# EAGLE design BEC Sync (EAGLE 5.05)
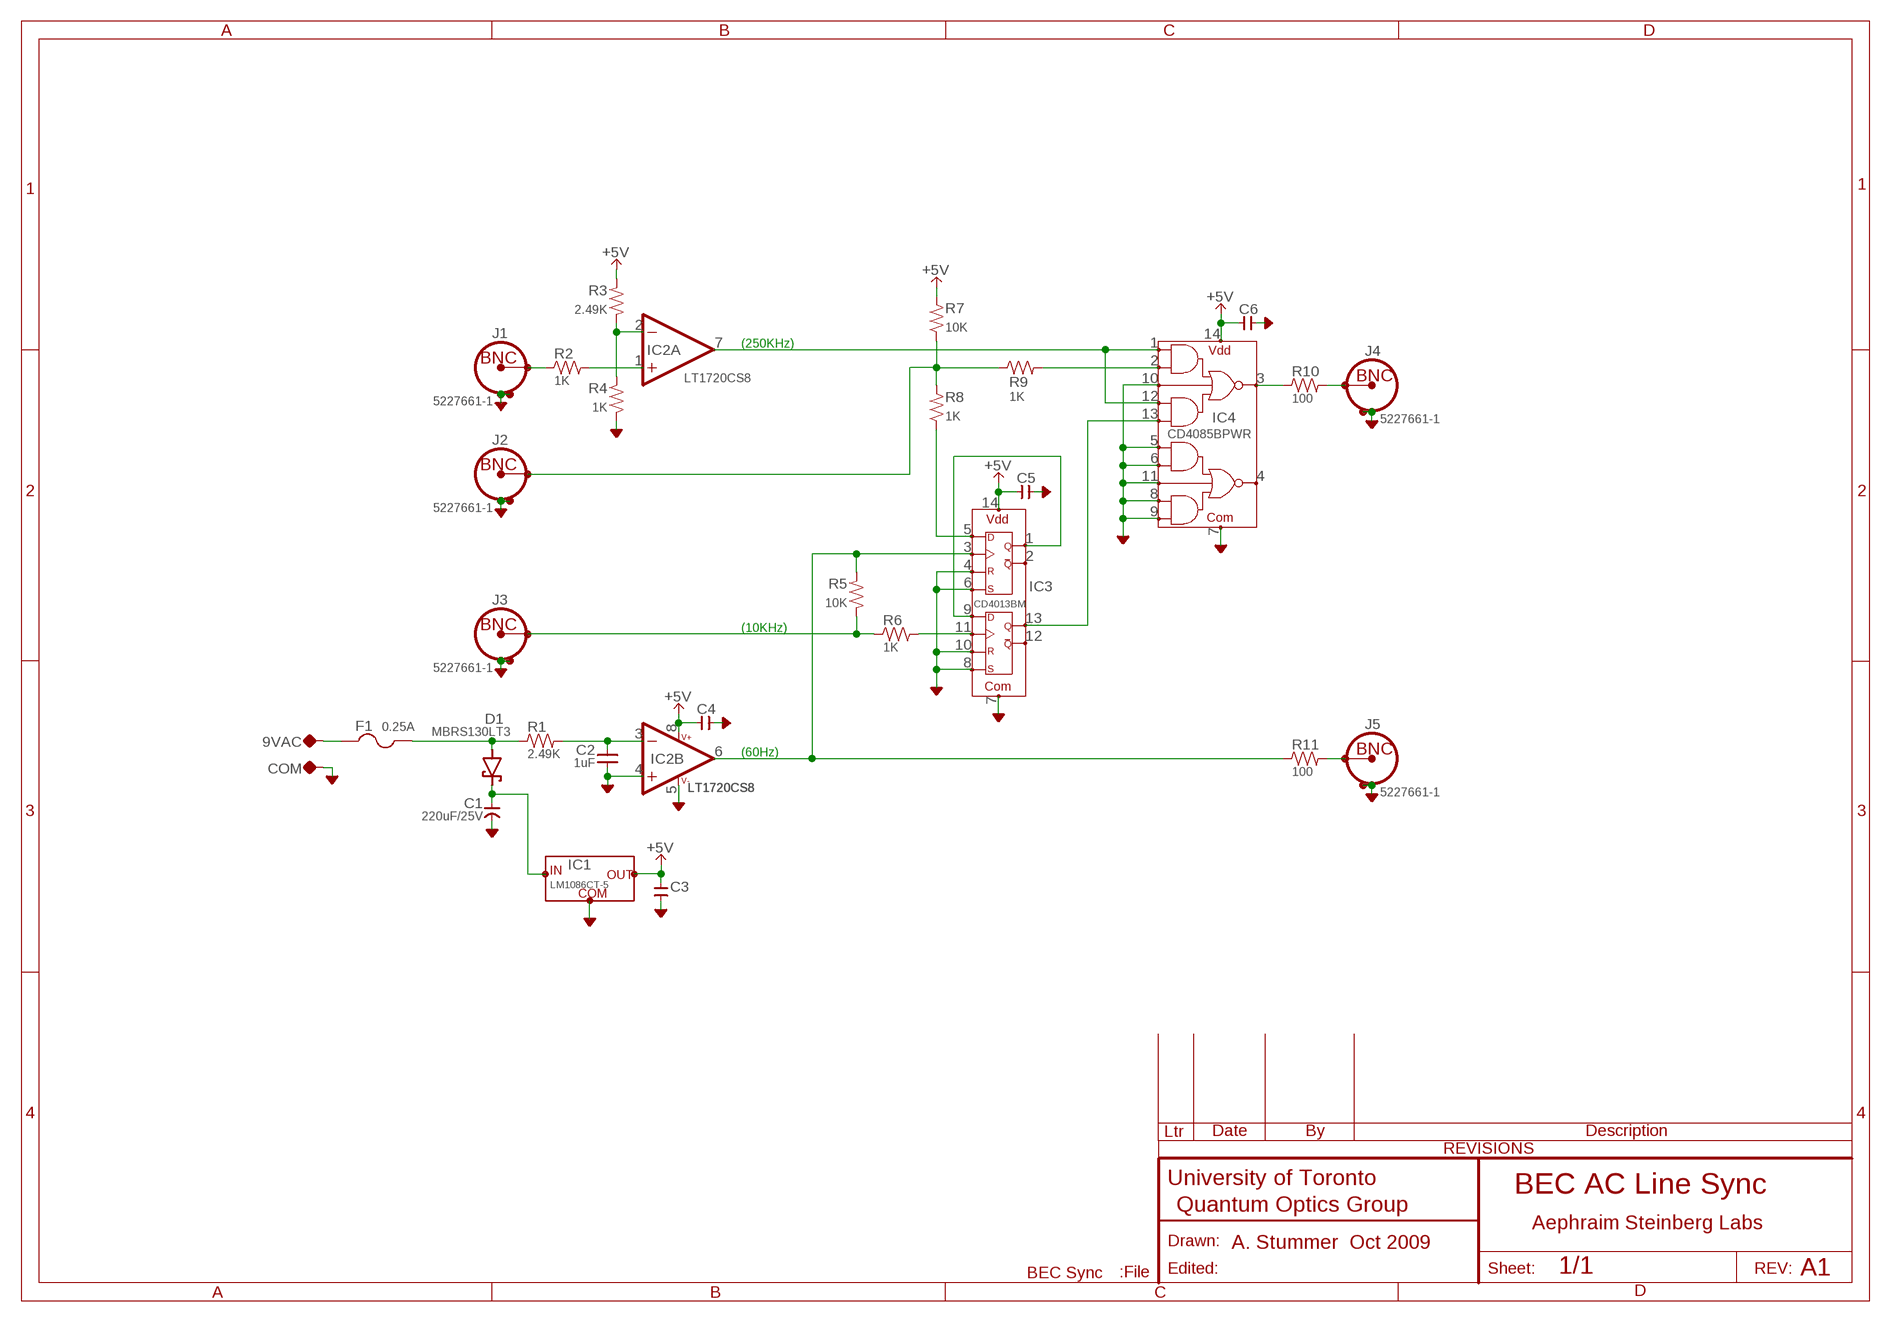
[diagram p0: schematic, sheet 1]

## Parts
9VAC  TP-0.042B  [TP-0.042B]
C1  220uF/25V  CAP-POL--NICHICON_UPW_8MM  [CAP:NICHICON_UPW-8MM]
C2  1uF  CAP-V-0805  [2012(0805)]
C3  0.1uF  CAP-H-0805  [2012(0805)]
C4  0.1uF  CAP-H-0805  [2012(0805)]
C5  0.1uF  CAP-H-0805  [2012(0805)]
C6  0.1uF  CAP-H-0805  [2012(0805)]
COM  TP-0.042B  [TP-0.042B]
D1  MBRS130LT3  DIODE,SCHOTTKY:MBRS130LT3(1A,30V)  [EIA-B(SMB)]
F1  0.25A  FUSE-5X20-4  [FUSE]
IC1  LM1086CT-5  REGULATOR:LM1086(LDO)-TO220(VERTICAL)  [TO220-VERTICAL]
IC2  LT1720CS8  COMPARATOR:LT1720(4.5NS,DUAL)CS8  [SOIC-8]
IC3  CD4013BM  LOGIC:D-FLIPFLOP,DUAL-SOIC14  [SOIC-14]
IC4  CD4085BPWR  LOGIC:AND-OR-INVERT,DUAL-TSSOP14  [TSSOP-14]
J1  5227661-1  CONN-BNCTYPE3HORIZ  [CONN-BNC-AMP-TYPE3HORIZ]
J2  5227661-1  CONN-BNCTYPE3HORIZ  [CONN-BNC-AMP-TYPE3HORIZ]
J3  5227661-1  CONN-BNCTYPE3HORIZ  [CONN-BNC-AMP-TYPE3HORIZ]
J4  5227661-1  CONN-BNCTYPE3HORIZ  [CONN-BNC-AMP-TYPE3HORIZ]
J5  5227661-1  CONN-BNCTYPE3HORIZ  [CONN-BNC-AMP-TYPE3HORIZ]
R1  2.49K  R-H-0805  [2012(0805)]
R2  1K  R-H-0805  [2012(0805)]
R3  2.49K  R-V-0805  [2012(0805)]
R4  1K  R-V-0805  [2012(0805)]
R5  10K  R-V-0805  [2012(0805)]
R6  1K  R-H-0805  [2012(0805)]
R7  10K  R-V-0805  [2012(0805)]
R8  1K  R-V-0805  [2012(0805)]
R9  1K  R-H-0805  [2012(0805)]
R10  100  R-H-0805  [2012(0805)]
R11  100  R-H-0805  [2012(0805)]

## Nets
+5V: C3.1 C4.1 C5.1 C6.1 IC1.2(OUT) IC2.8(V++) IC3.14(VDD) IC4.14(VDD) R3.2 R7.2
AGND: C1.-(NEG) C2.1 C3.2 C4.2 C5.2 C6.2 COM.TP IC1.1(COM) IC2.4(B:+IN) IC2.5(V-) IC3.4(R-A) IC3.6(S-A) IC3.7(COM) IC3.8(S-B) IC3.10(R-B) IC4.5(B1-1) IC4.6(B1-2) IC4.7(COM) IC4.8(B2-1) IC4.9(B2-2) IC4.10(A-INH) IC4.11(B-INH) J1.SHIELD1 J1.SHIELD2 J2.SHIELD1 J2.SHIELD2 J3.SHIELD1 J3.SHIELD2 J4.SHIELD1 J4.SHIELD2 J5.SHIELD1 J5.SHIELD2 R4.1
N$1: IC3.1(Q-A) IC3.9(D-B)
N$2: IC2.7(A:OUT) IC4.1(A1-1) IC4.12(A2-1)
N$3: IC3.13(Q-B) IC4.13(A2-2)
N$4: J2.CONDUCTOR R7.1 R8.2 R9.1
N$5: IC2.6(B:OUT) IC3.3(CLK-A) R5.2 R11.1
N$6: J3.CONDUCTOR R5.1 R6.1
N$7: J4.CONDUCTOR R10.2
N$8: IC3.11(CLK-B) R6.2
N$9: IC4.2(A1-2) R9.2
N$10: IC3.5(D-A) R8.1
N$11: IC4.3(QA) R10.1
N$12: J5.CONDUCTOR R11.2
N$13: IC2.1(A:+IN) R2.2
N$14: IC2.2(A:-IN) R3.1 R4.2
N$15: J1.CONDUCTOR R2.1
N$16: C2.2 IC2.3(B:-IN) R1.2
N$17: D1.A-(A) F1.2A R1.1
N$18: 9VAC.TP F1.1A
N$19: C1.+(POS) D1.K+(C) IC1.3(VI)
Unconnected: IC3.2(~Q-A) IC3.12(~Q-B) IC4.4(QB)

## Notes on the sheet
- (250KHz)
- (10KHz)
- (60Hz)
- BEC AC Line Sync
- Aephraim Steinberg Labs
- A. Stummer  Oct 2009
- A1

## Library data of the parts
9VAC COM = QuantumOptics:TP: Testpoint, either SMT pad, small hole or loop style TP such as Keystone 5002K (0.042").
C1 = QuantumOptics:CAP-POL-: Capacitor, Polarized, SMT 0805 and up, probably tantalum.
C2 = QuantumOptics:CAP-V-: Cap, SMT and Through-hole, 0402 and up.
C3-C6 = QuantumOptics:CAP-H-: Cap, SMT and Through-hole, 0402 and up.
D1 = QuantumOptics:DIODE,SCHOTTKY:MBRS130LT3(1A,30V): MBRS130LT3, ON Semi et al, schottky, 1A 30V, SMB. General purpose schottky in SMT.
F1 = QuantumOptics:FUSE: Fuse
IC1 = QuantumOptics:REGULATOR:LM1086(LDO): LM1086-xxx, National Semiconductor, LDO, adjustable or fixed. http://cache.national.com/ds/LM/LM1086.pdf
IC2 = QuantumOptics:COMPARATOR:LT1720(4.5NS,DUAL): Compatator, dual, fast (4.5nS), single supply.
IC3 = QuantumOptics:LOGIC:D-FLIPFLOP,DUAL: Classic dual D-type flip-flop, such as CD4013, http://www.fairchildsemi.com/ds/CD/CD4013BC.pdf
IC4 = QuantumOptics:LOGIC:AND-OR-INVERT,DUAL: Classic dual AND-OR-INVERT mux, such as CD4085, http://focus.ti.com/lit/ds/symlink/cd4085b.pdf
J1-J5 = QuantumOptics:CONN-BNC: BNC PCB, horizontal or vertical, e.g. Horiz: Amp (5)227677-1, nut 1-329631-2, shoulder washer 330620. The two shield connections allow the assembly on either side of the board. Vert isolated: 5227222-6, http://catalog.tycoelectronics.com/TE/bin/TE.Connect?C=1&M=BYPN&TCPN=5227222-6&RQPN=5227222-6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
R1 R2 R6 R9-R11 = QuantumOptics:R-H-*: Resistor, SMT & Through-Hole, horizontal symbol
R3-R5 R7 R8 = QuantumOptics:R-V-*: Resistor, SMT & Through-Hole, vertical symbol

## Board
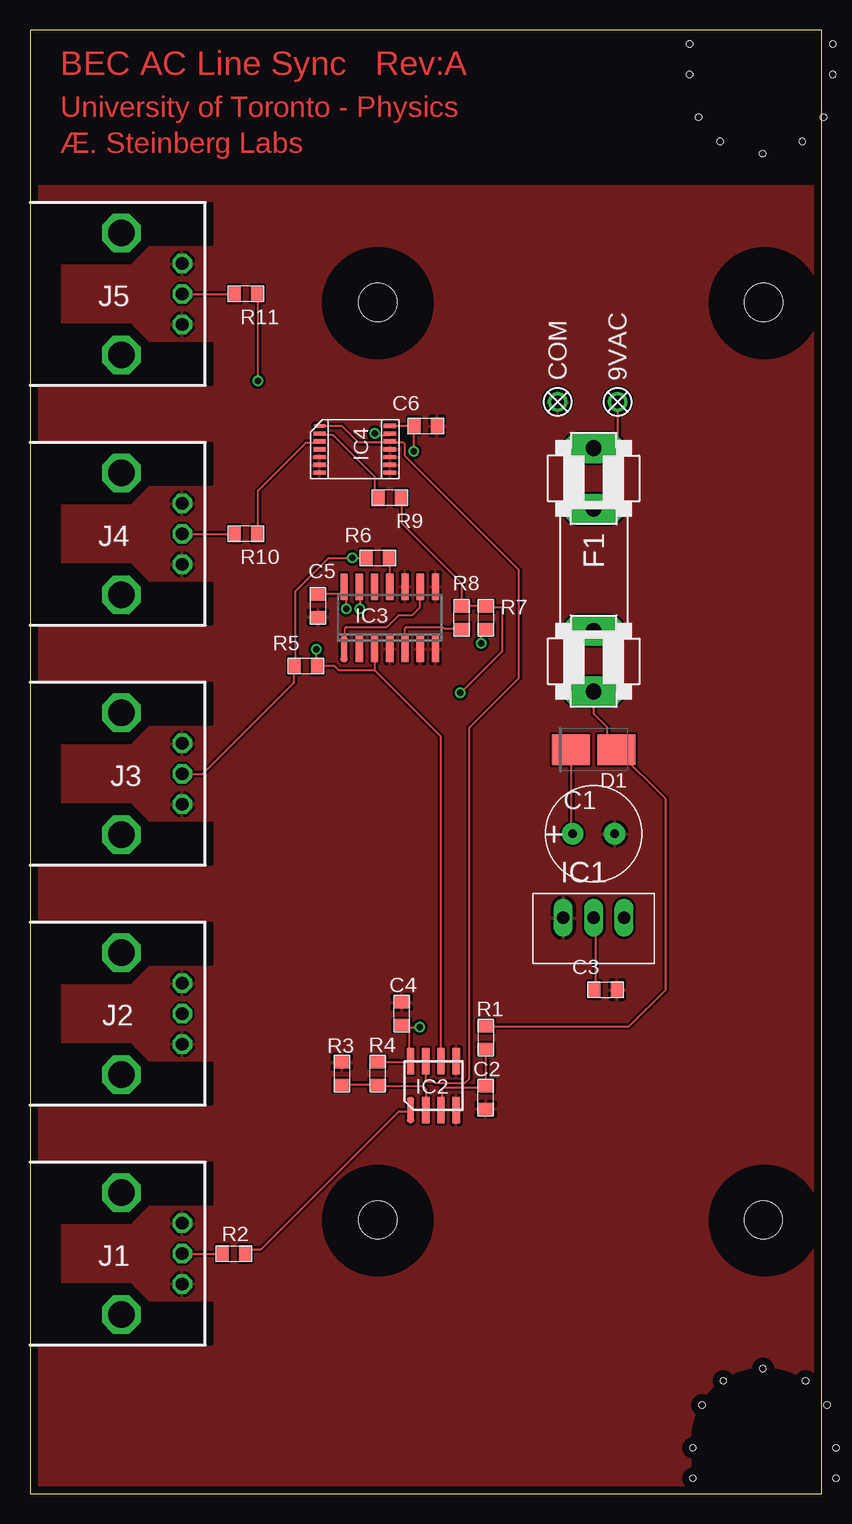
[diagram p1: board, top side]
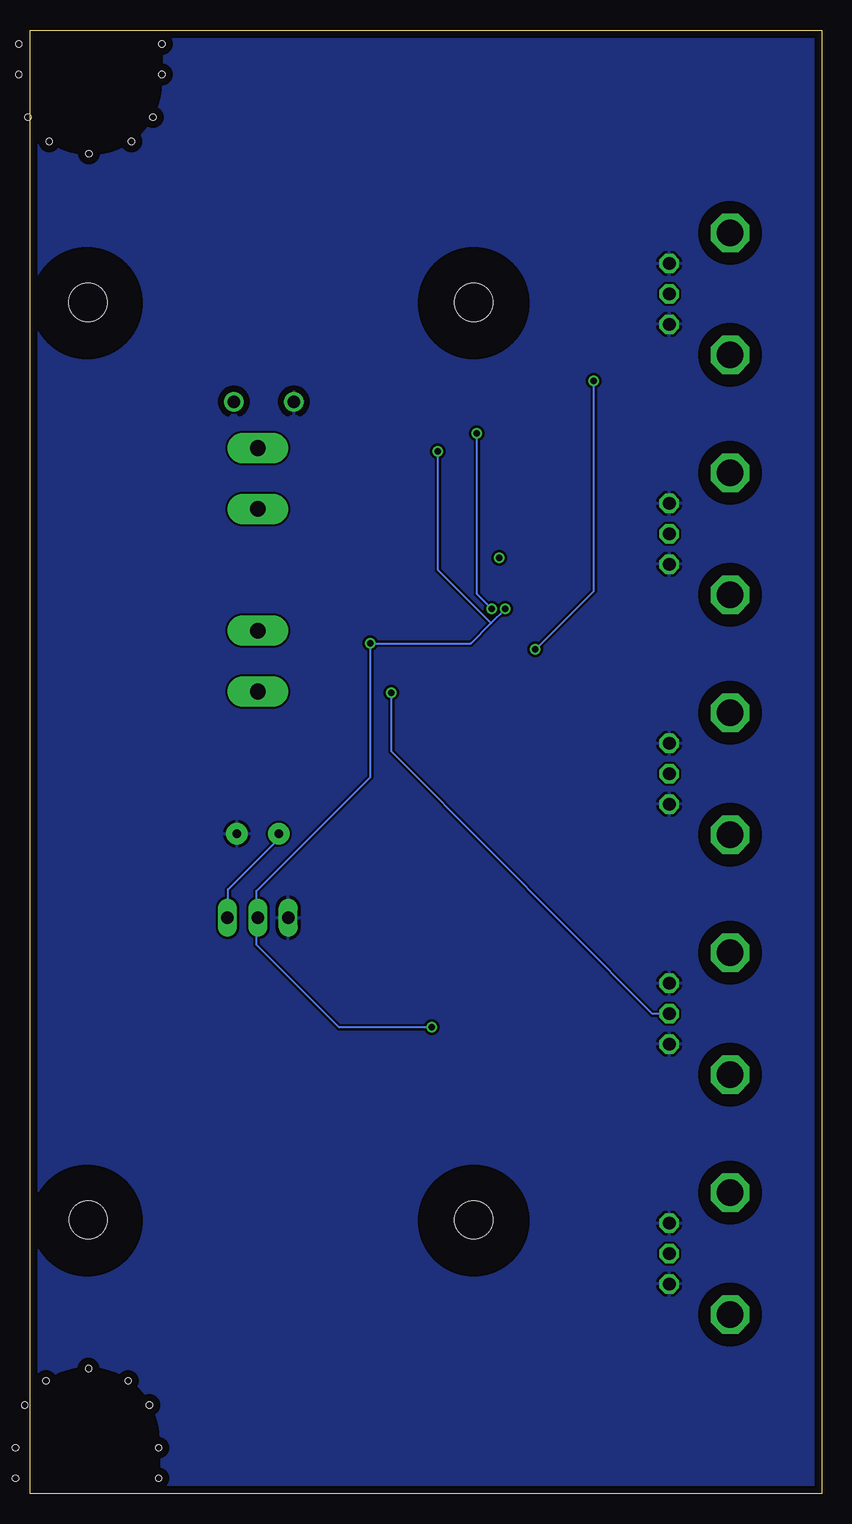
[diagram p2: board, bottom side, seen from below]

Size 66 x 122 mm. Coordinates in mm from the lower left corner, seen from the top.
Outline: 0,0 66,0 66,122 0,122 0,0
Copper layers (1+16): Top 0.035mm / dielectric 1.5mm / Bottom 0.035mm
Design rules "DRC standard check": minimum track width 7mil, minimum drill 20mil, track to track 7mil, track to pad 7mil, pad to pad 7mil, via to via 7mil, smd to smd 0mil, copper to edge 25mil, drill to drill 8mil, minimum pad ring 10mil, minimum via ring 8mil, stop-mask expansion 4mil, vias tented up to drill 0mil, thermal gap 10mil
Holes 3.17 mm at 29,22.81 61.15,22.82 29.01,99.29 61.16,99.3
tRestrict: area 24.4,18.2 to 33.6,27.3; area 56.7,18.2 to 65.8,27.3; area 24.4,94.7 to 33.6,103.8; area 56.7,94.7 to 65.8,103.8
bRestrict: area 24.4,18.2 to 33.6,27.3; area 56.7,18.2 to 65.8,27.3; area 24.4,94.7 to 33.6,103.8; area 56.7,94.7 to 65.8,103.8

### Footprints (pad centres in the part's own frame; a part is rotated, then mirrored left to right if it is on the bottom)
TP-0.042B = drill 1.067 round: TP 0,0
CAP:NICHICON_UPW-8MM = drill 0.711 pad 1.778 round: + -1.75,0; - 1.75,0
2012(0805) = smd 1.016 x 1.397: 1 -0.953,0; 2 0.953,0
EIA-B(SMB) = smd 3.175 x 2.54: A- -1.905,0; K+ 1.905,0
FUSE = drill 1.321 pad 2.54 long: 1A -10.16,0; 1B -5.08,0; 2A 10.16,0; 2B 5.08,0
TO220-VERTICAL = drill 1.067 long: 1 -2.54,0; 2 0,0; 3 2.54,0
SOIC-8 = smd 0.6 x 2.2: 1 -1.27,-2.032; 2 0,-2.032; 3 1.27,-2.032; 4 2.54,-2.032; 5 2.54,2.032; 6 1.27,2.032; 7 0,2.032; 8 -1.27,2.032
SOIC-14 = smd 0.6 x 2.2: 1 -3.81,-2.6; 2 -2.54,-2.6; 3 -1.27,-2.6; 4 0,-2.6; 5 1.27,-2.6; 6 2.54,-2.6; 7 3.81,-2.6; 8 3.81,2.6; 9 2.54,2.6; 10 1.27,2.6; 11 0,2.6; 12 -1.27,2.6; 13 -2.54,2.6; 14 -3.81,2.6
TSSOP-14 = smd 0.356 x 1.016: 1 0,-5.85; 2 0.65,-5.85; 3 1.3,-5.85; 4 1.95,-5.85; 5 2.6,-5.85; 6 3.25,-5.85; 7 3.9,-5.85; 8 3.9,0; 9 3.25,0; 10 2.6,0; 11 1.95,0; 12 1.3,0; 13 0.65,0; 14 0,0
CONN-BNC-AMP-TYPE3HORIZ = drill 1.067 octagon: CONDUCTOR 0,-12.7; SHIELD1 -2.54,-12.7; SHIELD2 2.54,-12.7 | drill 2.184 octagon: P$1 -5.08,-7.62; P$2 5.08,-7.62
CASE-HAMMOND-1598B = hole 0.508: 55.27,1.27; 55.27,3.81; 56.032,7.366; 57.81,9.398; 61.112,10.414; 64.668,9.398; 66.446,7.366; 67.208,3.81; 67.208,1.27; 66.93,120.83; 66.93,118.29; 66.168,114.734; 64.39,112.702; 61.088,111.686; 57.532,112.702; 55.754,114.734; 54.992,118.29; 54.992,120.83

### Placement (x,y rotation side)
9VAC  49,91 90 top
C1  47,55 0 top
C2  38,33 90 top
C3  48,42 0 top
C4  31,40 90 top
C5  24,74 270 top
C6  33,89 0 top
COM  44,91 90 top
D1  47,62 180 top
F1  47,77 270 top
IC1  47,48 0 top
IC2  33,34 0 top
IC3  30,73 0 top
IC4  30,89 270 top
J1  0,20 90 top
J2  0,40 90 top
J3  0,60 90 top
J4  0,80 90 top
J5  0,100 90 top
R1  38,38 270 top
R2  17,20 0 top
R3  29,35 90 top
R4  26,35 270 top
R5  23,69 0 top
R6  29,78 0 top
R7  38,73 270 top
R8  36,73 90 top
R9  30,83 180 top
R10  18,80 180 top
R11  18,100 180 top
U$20  [CASE-HAMMOND-1598B]  0,0 0 top

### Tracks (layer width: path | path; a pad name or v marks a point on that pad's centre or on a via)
+5V  (via drill 0.51)
  Top 0.178: 32,89 IC4.14 | C5.1 24,75 26,75 26.12,75.12 26.12,75.5 IC3.14 26.12,75 26.38,74.75 v26.38,73.75 | v37.62,70.88 37.62,71.62 38,72 R7.2 | v32,86.88 32,89 | 32,89 C6.1 | R3.2 29,36 31.62,36 IC2.8 31.62,36.12 31.62,38.62 31.25,39 31,39 C4.1 31.5,38.88 v32.5,38.88 | IC1.2 47.12,47.88 47.12,42 C3.1
  Bottom 0.178: 27.56,72.56 v26.38,73.75 | 27.56,72.56 29.25,70.88 v37.62,70.88 37.62,59.75 47.12,50.25 47.12,48 IC1.2 47.12,47.88 47.12,45.75 40.25,38.88 v32.5,38.88 | v32,86.88 32,77 27.56,72.56
AGND
  pour Bottom: 0,0 66,0 66,122 0,122
  pour Top: 0,0 66,0 66,109 0,109
N$1
  Top 0.178: 26.25,72.12 26.25,70.5 IC3.1 | 31.88,73.25 32.5,73.88 32.5,75.5 IC3.9
  Top 0.18: 31.88,73.25 30.75,73.25 29.75,72.25 26.38,72.25 26.25,72.12
N$2
  Top 0.178: 30,87.62 27.38,87.62 26,89 IC4.1 | 30,87.62 31.12,87.62 31.25,87.5 31.25,86.5 40.75,77 40.75,68 36.62,63.88 36.62,34.62 36.25,34.25 33.75,34.25 33.62,34.38 33,34.38 IC2.7 | 30,87.62 IC4.12
N$3  (via drill 0.51)
  Top 0.178: v28.75,88.38 28.88,88.25 30,88.25 IC4.13 | v27.5,73.75 27.5,75.5 IC3.13
  Bottom 0.178: v28.75,88.38 28.75,75 v27.5,73.75
N$4  (via drill 0.51)
  Top 0.178: 36,74 38,74 R7.1 38,73.88 39.38,73.88 39.38,70.25 v35.88,66.75 | 36,74 36,75.88 31,80.88 31,83 R9.1 | 36,74 R8.2
  Bottom 0.178: 35,61 14.12,40 J2.CONDUCTOR | v35.88,66.75 36,66.75
  Bottom 0.18: 35,61 35.88,61.88 v35.88,66.75
N$5  (via drill 0.51)
  Top 0.178: 18.88,100 R11.1 19,100 v19,92.75 | IC2.6 34.25,36.12 34.25,63.12 28.75,68.62 | 28.75,68.62 25.75,68.62 25.38,69 R5.2 23.88,69 v23.88,70.38 | 28.75,68.62 28.75,70.38 IC3.3
  Bottom 0.178: v19,92.75 19,75.25 v23.88,70.38
N$6  (via drill 0.51)
  Top 0.178: R6.1 v26.88,78 24.88,78 22.12,75.25 22.12,69 R5.1 22,69 22,67.62 14.38,60 J3.CONDUCTOR
N$7
  Top 0.178: J4.CONDUCTOR R10.2
N$8
  Top 0.178: R6.2 30,78 IC3.11
N$9
  Top 0.178: IC4.2 24.25,88.25 25.25,88.25 28.75,84.75 28.75,83.25 29,83 R9.2
N$10
  Top 0.178: R8.1 36,72.12 34.5,72.12 34.38,72.25 31.38,72.25 31.25,72.12 31.25,70.5 IC3.5
N$11
  Top 0.178: IC4.3 24.12,87.62 23,87.62 19,83.62 19,80 R10.1
N$12
  Top 0.178: J5.CONDUCTOR R11.2
N$13
  Top 0.178: R2.2 18,20 18.38,20.38 19.25,20.38 30.75,31.88 31.62,31.88 IC2.1
N$14
  Top 0.178: R4.2 26,34.12 29,34.12 R3.1 29,34 32.75,34 33,33.75 IC2.2
N$15
  Top 0.178: J1.CONDUCTOR R2.1
N$16
  Top 0.178: R1.2 C2.2 38,33.88 34.5,33.88 34.38,33.75 34.38,32 IC2.3
N$17
  Top 0.178: F1.2A 47,65 48.12,63.88 48.12,62.75 48.88,62 D1.A-
  Top 0.18: R1.1 49.95,38.95 53,42 53,57.91 D1.A-
N$18
  Top 0.178: 9VAC.TP 49,88.12 48.12,87.25 47,87.25 F1.1A
N$19
  Top 0.178: C1.+ 45.12,55.12 45.12,62 D1.K+
  Bottom 0.178: 45.12,54.75 49.5,50.38 49.5,48 IC1.3
  Bottom 0.18: 45.12,54.75 45.12,55.12 C1.+

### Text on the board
Top: BEC AC Line Sync Rev:A | University of Toronto - Physics | Æ. Steinberg Labs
